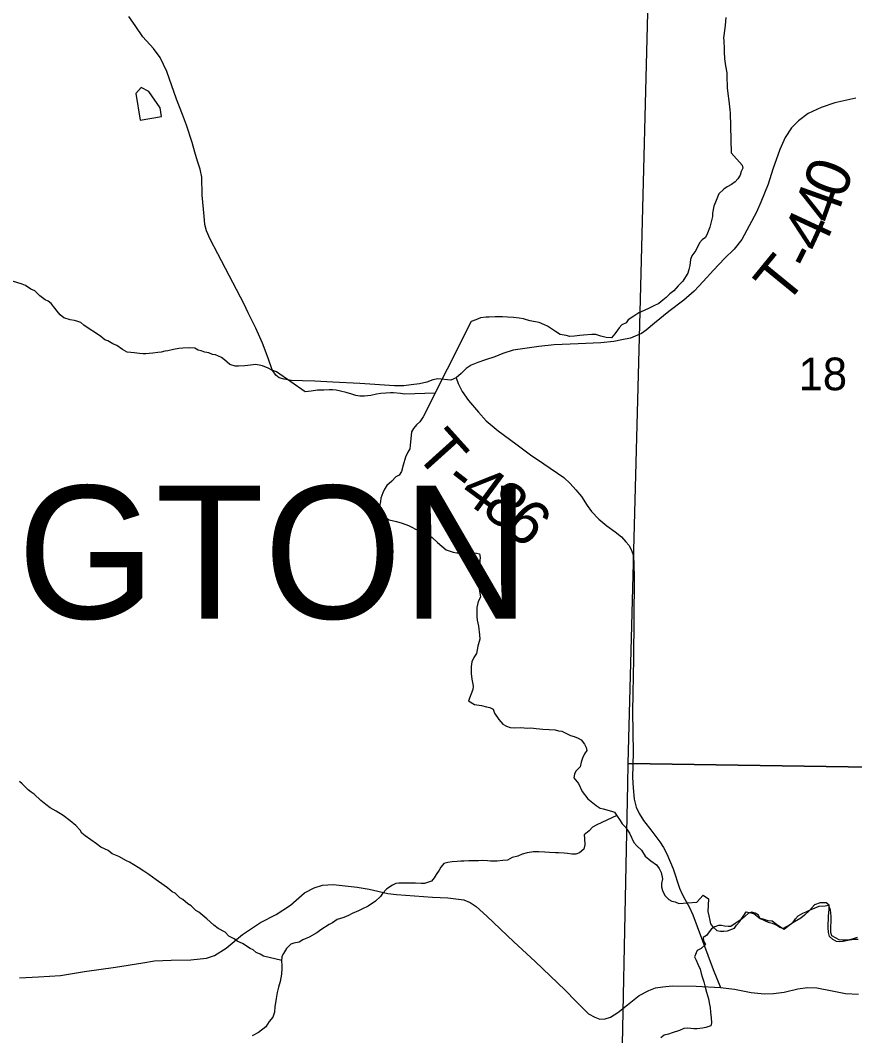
# Model space of a CAD drawing. Extents: x 0 to 34, y 0 to 22.
# Drawn here: x 27.873 to 28.944, y 18.536 to 19.839 of the extents above; entities that cross this region are included whole.
import ezdxf

# ---------------------------------------------------------------- set-up
doc = ezdxf.new("R2010")
doc.units = 0
for name, color, linetype in [('GM_X_County_Road', 7, 'Continuous'), ('GM_X_Minor_Lake', 7, 'Continuous'), ('GM_X_Minor_River', 7, 'Continuous'), ('GM_X_Section', 7, 'Continuous'), ('GM_X_Section_Text', 7, 'Continuous'), ('GM_X_Township_Road', 7, 'Continuous'), ('GM_X_Township_Road_Text', 7, 'Continuous'), ('GM_X_Township_Text', 7, 'Continuous')]:
    doc.layers.add(name, color=color, linetype=linetype)

msp = doc.modelspace()

# ---------------------------------------------------------------- linework, layer by layer
at = {"layer": 'GM_X_County_Road'}
msp.add_lwpolyline([(27.8718, 18.6103), (27.8963, 18.6115), (27.9246, 18.6134), (27.9554, 18.6182), (27.9952, 18.6241), (28.0303, 18.6296), (28.0452, 18.6319), (28.0665, 18.6331), (28.0918, 18.6335), (28.1119, 18.6355), (28.1221, 18.639), (28.1371, 18.6485), (28.158, 18.6658), (28.1812, 18.6812), (28.2013, 18.6915), (28.2199, 18.7033), (28.2376, 18.7191), (28.2502, 18.7258), (28.2609, 18.7293), (28.2746, 18.7301), (28.3055, 18.7264), (28.3209, 18.7239), (28.3448, 18.7183), (28.3559, 18.7172), (28.402, 18.7139), (28.4217, 18.7131), (28.4421, 18.7102), (28.4505, 18.7067), (28.4583, 18.7017), (28.4717, 18.6895), (28.5064, 18.6564), (28.5339, 18.631), (28.5722, 18.5943), (28.5863, 18.5803), (28.6022, 18.564), (28.6104, 18.5597), (28.6171, 18.5573), (28.6238, 18.5575), (28.6304, 18.5598), (28.6402, 18.5657), (28.6524, 18.5757), (28.6673, 18.5877), (28.6798, 18.5941), (28.6884, 18.5975), (28.6978, 18.5987), (28.7096, 18.5998), (28.7408, 18.5995), (28.7718, 18.5979), (28.7899, 18.5956), (28.811, 18.5915), (28.8283, 18.5899), (28.8399, 18.5903), (28.8535, 18.592), (28.8712, 18.5962), (28.8836, 18.598), (28.8957, 18.5972), (28.915, 18.5937), (28.9324, 18.5903), (28.949, 18.5892)], dxfattribs=at)
at = {"layer": 'GM_X_Minor_Lake'}
for points in [[(28.0524, 19.7268), (28.0379, 19.7476), (28.028, 19.7529), (28.0212, 19.7449), (28.0266, 19.7108)], [(28.0266, 19.7108), (28.0543, 19.7154), (28.0524, 19.7268)]]:
    msp.add_lwpolyline(points, dxfattribs=at)
at = {"layer": 'GM_X_Minor_River'}
for points in [[(28.7788, 19.8424), (28.7777, 19.8329), (28.7773, 19.8288), (28.7758, 19.8166), (28.7762, 19.8128), (28.7766, 19.8026), (28.7766, 19.7984), (28.777, 19.7897), (28.7782, 19.7806), (28.7801, 19.7715), (28.7801, 19.7669), (28.7801, 19.7632), (28.7802, 19.7571), (28.7806, 19.7522), (28.7813, 19.745), (28.7825, 19.7355), (28.7837, 19.7241), (28.7844, 19.7199), (28.7854, 19.6688), (28.7998, 19.6529), (28.8006, 19.6491), (28.7983, 19.6449), (28.7972, 19.6403), (28.7942, 19.6354), (28.7908, 19.6316), (28.7859, 19.6282), (28.7806, 19.6255), (28.776, 19.6225), (28.7696, 19.6164), (28.7662, 19.6077), (28.7632, 19.6005), (28.7617, 19.5914), (28.7614, 19.5872), (28.7599, 19.5804), (28.758, 19.5735), (28.755, 19.5659), (28.7524, 19.5602), (28.7482, 19.5572), (28.7448, 19.5534), (28.7403, 19.5435), (28.735, 19.5367), (28.7335, 19.5321), (28.7324, 19.5242)], [(28.7324, 19.5242), (28.7313, 19.5192), (28.7298, 19.5147), (28.7271, 19.5098), (28.7233, 19.5041), (28.7173, 19.4984), (28.712, 19.4919), (28.7067, 19.4881), (28.7022, 19.4835), (28.698, 19.4797), (28.6927, 19.4756), (28.6852, 19.4721), (28.6803, 19.4695), (28.6738, 19.4668), (28.667, 19.4634), (28.6606, 19.4592), (28.6534, 19.4546), (28.6508, 19.4508), (28.6451, 19.4482), (28.6417, 19.4444), (28.636, 19.4368), (28.6319, 19.4314), (28.625, 19.4318), (28.6182, 19.4337), (28.6118, 19.4356), (28.6065, 19.4356), (28.5959, 19.4348), (28.5913, 19.4344), (28.5845, 19.4336), (28.5784, 19.4332), (28.5735, 19.4344), (28.5659, 19.4359), (28.5598, 19.4396), (28.5549, 19.443), (28.5496, 19.4464), (28.5458, 19.4483), (28.539, 19.4514), (28.5318, 19.4525), (28.5276, 19.4532), (28.5227, 19.4547), (28.5189, 19.4559), (28.5132, 19.4566), (28.506, 19.4577), (28.4984, 19.4581), (28.492, 19.4585), (28.4825, 19.4584), (28.4749, 19.458), (28.4711, 19.458), (28.4636, 19.4573), (28.4579, 19.4546), (28.4518, 19.4523), (28.39, 19.3301), (28.3859, 19.3236), (28.3817, 19.3198), (28.3776, 19.3153), (28.375, 19.3107), (28.3735, 19.2933), (28.3731, 19.2891), (28.3705, 19.2849), (28.3675, 19.2784), (28.3645, 19.2682), (28.3622, 19.2599), (28.3592, 19.2553), (28.355, 19.253), (28.3498, 19.2477), (28.3433, 19.242), (28.3403, 19.2374), (28.3381, 19.2325), (28.3358, 19.2257), (28.3354, 19.2215), (28.3343, 19.2177), (28.3343, 19.2139), (28.3343, 19.2101), (28.3355, 19.2063), (28.34, 19.2018), (28.3465, 19.198), (28.356, 19.1958), (28.3632, 19.1935), (28.3711, 19.1905), (28.3757, 19.1886), (28.3803, 19.1859), (28.3844, 19.1844), (28.3882, 19.1829), (28.3962, 19.1795), (28.4015, 19.1754), (28.4083, 19.1689), (28.4194, 19.1595), (28.4285, 19.1565), (28.4334, 19.1557), (28.4398, 19.1557), (28.4501, 19.1561), (28.4584, 19.1554), (28.4626, 19.1543), (28.4633, 19.1497), (28.4626, 19.1417), (28.4619, 19.1342), (28.4611, 19.1288), (28.4616, 19.1122), (28.4635, 19.0989), (28.4609, 19.0932), (28.459, 19.0856)], [(28.4054, 19.3605), (28.3661, 19.3592), (28.3608, 19.36), (28.3521, 19.3611), (28.3483, 19.3611), (28.3422, 19.3607), (28.3358, 19.3599), (28.3301, 19.3591), (28.3229, 19.3576), (28.3187, 19.3572), (28.3149, 19.3568), (28.3089, 19.3568), (28.3036, 19.3576), (28.2986, 19.3591), (28.2914, 19.3613), (28.2839, 19.3632), (28.2785, 19.3643), (28.2736, 19.3647), (28.2694, 19.3647), (28.2626, 19.3643), (28.2543, 19.3643), (28.2463, 19.3631), (28.2426, 19.3628), (28.2384, 19.3624), (28.2019, 19.3877), (28.1959, 19.39), (28.1909, 19.3926), (28.1837, 19.3956), (28.1754, 19.3971), (28.1716, 19.3967), (28.1648, 19.396), (28.161, 19.3956), (28.153, 19.3952), (28.1485, 19.3952), (28.142, 19.3971), (28.1348, 19.4031), (28.131, 19.4065), (28.1234, 19.4095), (28.1196, 19.4103), (28.1147, 19.4122), (28.1098, 19.4133), (28.1052, 19.4148), (28.1011, 19.4159), (28.0969, 19.4182), (28.0897, 19.4186), (28.0813, 19.4182), (28.0764, 19.4178), (28.0696, 19.4166), (28.0624, 19.4147), (28.0582, 19.4143), (28.0537, 19.4132), (28.0495, 19.4128), (28.0431, 19.412), (28.0382, 19.4116), (28.034, 19.4112), (28.0302, 19.4112), (28.0257, 19.4116), (28.0192, 19.4123), (28.0147, 19.4127), (28.0101, 19.4131), (28.004, 19.4165), (27.9968, 19.4218), (27.9915, 19.424), (27.9851, 19.4278), (27.9813, 19.429), (27.9763, 19.4331), (27.9695, 19.438), (27.9611, 19.4429), (27.9543, 19.4479), (27.9505, 19.4513), (27.9467, 19.4524), (27.9425, 19.4539), (27.9369, 19.4546), (27.9289, 19.4573), (27.924, 19.4611), (27.9202, 19.4656), (27.9171, 19.4698), (27.9125, 19.4758), (27.9084, 19.4785), (27.9046, 19.4804), (27.8977, 19.4853), (27.8913, 19.4917), (27.8863, 19.494), (27.8795, 19.4989), (27.8753, 19.5004), (27.8628, 19.5042)], [(28.459, 19.0856), (28.459, 19.0739), (28.4594, 19.0693), (28.461, 19.0617), (28.4625, 19.0503), (28.4629, 19.045), (28.4603, 19.0359), (28.4584, 19.0264), (28.455, 19.0215), (28.4524, 19.0158), (28.4516, 19.0097), (28.4517, 19.0006), (28.4525, 18.9934), (28.4536, 18.9893), (28.4544, 18.9847), (28.454, 18.9802), (28.4484, 18.9657), (28.456, 18.9612), (28.4651, 18.9597), (28.4715, 18.9582), (28.4757, 18.9571), (28.4799, 18.9552), (28.4818, 18.9499), (28.4871, 18.9419), (28.4924, 18.9359), (28.497, 18.9332), (28.5019, 18.9313), (28.5076, 18.931), (28.5152, 18.9314), (28.5243, 18.9306), (28.5284, 18.931), (28.5352, 18.9303), (28.5436, 18.9292), (28.5519, 18.9288), (28.5595, 18.9284), (28.5637, 18.9273), (28.5682, 18.9266), (28.5792, 18.9213), (28.5838, 18.9198), (28.5891, 18.9179), (28.5929, 18.9156), (28.5971, 18.9099), (28.5994, 18.9058), (28.6001, 18.902), (28.5971, 18.8978), (28.5945, 18.8921), (28.593, 18.8868), (28.5915, 18.8811), (28.5862, 18.8754), (28.5843, 18.8716), (28.5836, 18.8667), (28.5896, 18.8595), (28.5942, 18.8492), (28.6015, 18.8398), (28.6121, 18.8315), (28.6174, 18.8281), (28.6212, 18.8269), (28.6318, 18.8243), (28.6356, 18.8228), (28.6383, 18.819), (28.6428, 18.8122), (28.6455, 18.808), (28.6497, 18.8035), (28.655, 18.7959), (28.6607, 18.7838), (28.6645, 18.7796), (28.6702, 18.7739), (28.6752, 18.7664), (28.6824, 18.7603), (28.6896, 18.7554), (28.693, 18.7505), (28.6957, 18.7452), (28.6972, 18.7372), (28.6961, 18.7311), (28.6961, 18.727), (28.6973, 18.7224), (28.7003, 18.716), (28.7053, 18.7107), (28.7095, 18.7088), (28.7136, 18.7077), (28.7182, 18.7058), (28.7413, 18.7073), (28.7496, 18.7165), (28.7564, 18.7115), (28.7557, 18.6952), (28.7569, 18.6899), (28.758, 18.6839), (28.7592, 18.6797), (28.7615, 18.6759), (28.7672, 18.671), (28.7717, 18.6699), (28.7759, 18.6699), (28.7808, 18.6706), (28.7899, 18.6741), (28.7925, 18.6779), (28.7963, 18.6821), (28.799, 18.6859), (28.8016, 18.6904), (28.805, 18.695), (28.8145, 18.6927), (28.819, 18.6893)], [(28.2085, 18.6325), (28.1852, 18.6382), (28.1807, 18.6405), (28.1758, 18.6428), (28.1716, 18.6462), (28.1678, 18.6477), (28.1579, 18.6541), (28.1511, 18.6571), (28.1473, 18.6601), (28.1405, 18.6639), (28.1359, 18.6688), (28.1268, 18.6734), (28.1215, 18.6779), (28.1123, 18.6859), (28.1021, 18.6946), (28.0983, 18.6968), (28.0922, 18.7025), (28.088, 18.7051), (28.0816, 18.7108), (28.0778, 18.7131), (28.0717, 18.7188), (28.0679, 18.7207), (28.0618, 18.7259), (28.0577, 18.7286), (28.0474, 18.7362), (28.0379, 18.743), (28.0315, 18.7471), (28.0242, 18.7517), (28.0129, 18.7588), (28.0091, 18.7604), (27.9992, 18.766), (27.9908, 18.7694), (27.9855, 18.7736), (27.9764, 18.7781), (27.9707, 18.7823), (27.9559, 18.7925), (27.9517, 18.7959), (27.9495, 18.7997), (27.9441, 18.8057), (27.9369, 18.8118), (27.9278, 18.8186), (27.9187, 18.8239), (27.9111, 18.8284), (27.9054, 18.8326), (27.8993, 18.8379), (27.8906, 18.8458), (27.8868, 18.8485), (27.883, 18.8515), (27.8754, 18.8591), (27.8716, 18.8621)], [(28.6386, 18.8185), (28.6129, 18.8064), (28.6076, 18.8034), (28.6031, 18.7988), (28.597, 18.7939), (28.5974, 18.789), (28.5975, 18.781), (28.5963, 18.7753), (28.591, 18.7707), (28.5861, 18.7688), (28.5808, 18.7688), (28.5755, 18.7696), (28.571, 18.7703), (28.5638, 18.7707), (28.56, 18.7707), (28.5524, 18.771), (28.5463, 18.7714), (28.5384, 18.7721), (28.5319, 18.7721), (28.5236, 18.7706), (28.5172, 18.7691), (28.5115, 18.7664), (28.5043, 18.7645), (28.4982, 18.7614), (28.4922, 18.761), (28.485, 18.7599), (28.4766, 18.7599), (28.4725, 18.7602), (28.4668, 18.7606), (28.4611, 18.7602), (28.4486, 18.7602), (28.4422, 18.7598), (28.4384, 18.7598), (28.4338, 18.7594), (28.4274, 18.759), (28.4217, 18.7582), (28.4164, 18.7571), (28.4126, 18.7521), (28.4107, 18.7483), (28.4066, 18.743), (28.404, 18.7385), (28.4009, 18.7343), (28.3919, 18.7312), (28.3877, 18.7312), (28.3801, 18.7316), (28.3744, 18.7319), (28.3642, 18.7319), (28.3589, 18.7315), (28.3551, 18.7311), (28.3509, 18.7292), (28.3434, 18.7243), (28.3377, 18.7186), (28.3351, 18.7144), (28.329, 18.7087), (28.3196, 18.7022), (28.312, 18.6988), (28.3071, 18.6961), (28.2991, 18.6927), (28.2942, 18.6904), (28.2882, 18.6878), (28.2798, 18.6851), (28.2738, 18.6809), (28.2692, 18.6786), (28.2586, 18.6718), (28.2537, 18.668), (28.2435, 18.6622), (28.2356, 18.6588), (28.2307, 18.6561), (28.2242, 18.6546), (28.2201, 18.6535), (28.2148, 18.6478), (28.2106, 18.6413), (28.2087, 18.6375), (28.2084, 18.6311), (28.2088, 18.6269), (28.2088, 18.622), (28.2084, 18.6148), (28.2066, 18.6056), (28.2043, 18.5984), (28.2028, 18.5916), (28.2013, 18.5836), (28.1998, 18.573), (28.1991, 18.5662), (28.1972, 18.5597), (28.1923, 18.554), (28.1882, 18.5472), (28.1787, 18.54), (28.1704, 18.5358)], [(28.819, 18.6893), (28.8228, 18.6863), (28.8285, 18.684), (28.8331, 18.6818), (28.838, 18.6803), (28.8441, 18.6776), (28.8482, 18.6753), (28.852, 18.6735), (28.8611, 18.6788), (28.8653, 18.6818), (28.8683, 18.686), (28.8717, 18.6898), (28.8774, 18.6932), (28.8819, 18.6948), (28.8861, 18.697), (28.8902, 18.6989), (28.8986, 18.7024), (28.9061, 18.7028), (28.9103, 18.7035), (28.9126, 18.6975), (28.9134, 18.6891), (28.9134, 18.6823), (28.913, 18.6762), (28.9131, 18.669), (28.9142, 18.6645), (28.9191, 18.6618), (28.9237, 18.6596), (28.9286, 18.6592), (28.9354, 18.6592), (28.9411, 18.6604), (28.9476, 18.6623)], [(28.9487, 18.6593), (28.9434, 18.6596), (28.9373, 18.6585), (28.9294, 18.6569), (28.9245, 18.6565), (28.9207, 18.6569), (28.9161, 18.6596), (28.9119, 18.6633), (28.9104, 18.6686), (28.91, 18.6747), (28.9107, 18.6899), (28.9115, 18.6979), (28.9114, 18.7035), (28.9073, 18.7066), (28.8997, 18.7066), (28.8925, 18.7039), (28.8861, 18.6967), (28.8796, 18.6906), (28.8751, 18.6868), (28.8668, 18.6822), (28.8622, 18.6792), (28.8581, 18.6761), (28.8536, 18.6723), (28.8479, 18.6757), (28.8437, 18.6787), (28.838, 18.6829), (28.8331, 18.6833), (28.8266, 18.6855), (28.8228, 18.6863)], [(28.8228, 18.6863), (28.8205, 18.6908), (28.8164, 18.6931), (28.8118, 18.6946), (28.8073, 18.6927), (28.7997, 18.6859), (28.7906, 18.6798), (28.7853, 18.6763), (28.7815, 18.676), (28.777, 18.6767), (28.7732, 18.6775), (28.7694, 18.6774), (28.7645, 18.6755), (28.7603, 18.6729), (28.7573, 18.6691), (28.7539, 18.6645), (28.7494, 18.6618), (28.7502, 18.6573), (28.7524, 18.6531), (28.7468, 18.6478), (28.7419, 18.6451), (28.7385, 18.6372), (28.7408, 18.633), (28.7427, 18.6277), (28.7457, 18.6213), (28.7469, 18.6159), (28.7484, 18.6114), (28.7503, 18.6053), (28.7518, 18.6), (28.7538, 18.5917), (28.7564, 18.5833), (28.7576, 18.5761), (28.7584, 18.572), (28.7591, 18.5663), (28.7599, 18.5591), (28.7603, 18.5523), (28.7596, 18.5485), (28.7528, 18.5465), (28.7486, 18.5458), (28.7418, 18.5446), (28.7376, 18.5446), (28.7338, 18.5454), (28.7289, 18.5457), (28.7247, 18.545), (28.7194, 18.5427), (28.7096, 18.5396), (28.705, 18.5381), (28.6994, 18.5366), (28.6952, 18.5331)]]:
    msp.add_lwpolyline(points, dxfattribs=at)
at = {"layer": 'GM_X_Section'}
for points in [[(28.6801, 19.9157), (29.153, 19.9086), (29.1334, 18.8778), (28.6533, 18.8853), (28.6686, 19.4646)], [(28.6533, 18.8853), (29.1334, 18.8778), (29.1338, 17.8638), (28.8761, 17.867), (28.6324, 17.87), (28.6432, 18.3787), (28.6528, 18.8587)]]:
    msp.add_lwpolyline(points, close=True, dxfattribs=at)
at = {"layer": 'GM_X_Township_Road'}
for points in [[(28.9454, 19.7389), (28.9185, 19.733), (28.9011, 19.7271), (28.8843, 19.7192), (28.8718, 19.71), (28.8632, 19.7011), (28.8549, 19.6885), (28.8479, 19.673), (28.839, 19.6481), (28.8329, 19.6289), (28.8238, 19.6055), (28.8182, 19.593), (28.7991, 19.5576), (28.7893, 19.5454), (28.7769, 19.5333), (28.763, 19.5183), (28.7494, 19.5037), (28.7382, 19.4915), (28.7246, 19.48), (28.7054, 19.4655), (28.6873, 19.4502), (28.6765, 19.4414), (28.6704, 19.4369), (28.6564, 19.4313), (28.6453, 19.4289), (28.6348, 19.4268), (28.6184, 19.4252), (28.5891, 19.4238), (28.5581, 19.4226), (28.5384, 19.4205), (28.5056, 19.4156), (28.4925, 19.4116), (28.482, 19.4071), (28.47, 19.4032), (28.4603, 19.3999), (28.4518, 19.3965), (28.4454, 19.392), (28.4389, 19.3856), (28.4324, 19.3801), (28.4255, 19.3774), (28.4091, 19.379), (28.4024, 19.3778), (28.3948, 19.3748), (28.3854, 19.3727), (28.3745, 19.3711), (28.3653, 19.37), (28.3533, 19.37), (28.3086, 19.373), (28.2742, 19.3746), (28.251, 19.376), (28.2353, 19.3764), (28.221, 19.3769), (28.2118, 19.3783), (28.2051, 19.3803), (28.2007, 19.3836), (28.1961, 19.3905), (28.191, 19.4055), (28.1839, 19.4248), (28.1753, 19.444), (28.1652, 19.4636), (28.1601, 19.4746), (28.1265, 19.5394), (28.1165, 19.5581), (28.1119, 19.5687), (28.1099, 19.577), (28.1087, 19.5876), (28.1064, 19.6146), (28.1057, 19.6379), (28.1039, 19.6478), (28.1004, 19.6584), (28.0967, 19.6699), (28.0935, 19.6824), (28.0861, 19.7043), (28.081, 19.7181), (28.0732, 19.7379), (28.0608, 19.7734), (28.0522, 19.7914), (28.0437, 19.8027), (28.0303, 19.8179), (28.0202, 19.8325), (28.0123, 19.844)], [(28.4324, 19.3801), (28.4352, 19.373), (28.44, 19.3628), (28.4481, 19.3513), (28.461, 19.3361), (28.4709, 19.3252), (28.4864, 19.3121), (28.509, 19.2955), (28.5279, 19.2814), (28.5452, 19.2699), (28.5705, 19.2522), (28.5788, 19.2448), (28.586, 19.2365), (28.5933, 19.2277), (28.6005, 19.2162), (28.606, 19.2088), (28.6155, 19.1987), (28.6261, 19.1901), (28.6364, 19.1825), (28.6448, 19.1761), (28.6505, 19.1698), (28.6542, 19.1655), (28.657, 19.1599), (28.6595, 19.153), (28.6607, 19.1438), (28.6611, 19.1212), (28.6604, 19.0714), (28.66, 19.0198), (28.6593, 18.975), (28.659, 18.9517), (28.6595, 18.8992), (28.659, 18.8671), (28.6595, 18.854), (28.6609, 18.8395), (28.6637, 18.8293), (28.6673, 18.8212), (28.6729, 18.812), (28.6835, 18.7984), (28.6941, 18.7848), (28.6987, 18.7774), (28.7031, 18.7694), (28.7111, 18.7502), (28.7194, 18.7253), (28.7224, 18.7184), (28.7261, 18.711), (28.7314, 18.7012), (28.7363, 18.691), (28.742, 18.6763), (28.7623, 18.6209), (28.7718, 18.5979)]]:
    msp.add_lwpolyline(points, dxfattribs=at)

# ---------------------------------------------------------------- texts
at = {"layer": 'GM_X_Section_Text'}
msp.add_text('18', height=0.04186, rotation=0, dxfattribs=at).set_placement((28.8721, 19.3643))
at = {"layer": 'GM_X_Township_Road_Text'}
for s, rotation, p in [('0', 69.193, (28.9292, 19.6079)), ('4', 70.3249, (28.9175, 19.5753)), ('4', 65.1475, (28.9007, 19.5383)), ('-', 63.0246, (28.8891, 19.5155)), ('T', 50.7733, (28.855, 19.4715)), ('T', 312.0016, (28.3779, 19.2824)), ('-', 322.3644, (28.4145, 19.2432)), ('4', 323.67, (28.4341, 19.2281)), ('8', 324.8649, (28.4633, 19.2066)), ('6', 319.3756, (28.4908, 19.1873))]:
    msp.add_text(s, height=0.0568, rotation=rotation, dxfattribs=at).set_placement(p)
at = {"layer": 'GM_X_Township_Text'}
msp.add_text('WASHINGTON', height=0.17045, rotation=0, dxfattribs=at).set_placement((26.9574, 19.0712))

doc.saveas('drawing.dxf')
